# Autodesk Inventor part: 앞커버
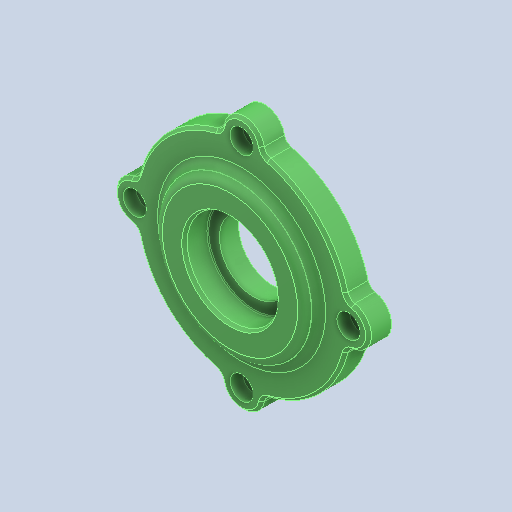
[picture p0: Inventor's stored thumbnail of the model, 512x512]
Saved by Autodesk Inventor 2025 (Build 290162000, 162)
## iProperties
Created: 2024-08
Part Number: 앞커버
Material: 알루미늄 6061
Document SubType Name: Modeling
Designer: 학생
Density: 2.71 g/cm^3
Appearance: 기본값
Company: 한국ATC센터
Author: jhkim
Sending System: Autodesk Inventor 2025
Preprocessor: ST-DEVELOPER v20
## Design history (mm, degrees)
feature "솔리드1"
node "솔리드2"
